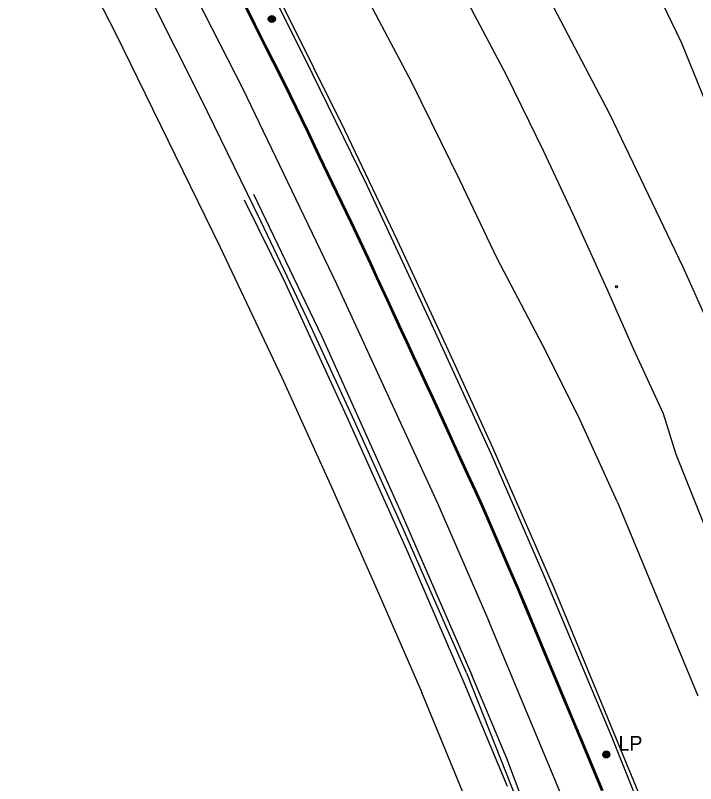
# Model space of a CAD drawing. Extents: x 368532 to 392481, y 10654822 to 10676899.
# Drawn here: x 370984.5 to 371215.5, y 10673594.7 to 10673855.7 of the extents above; entities that cross this region are included whole.
import ezdxf

# ---------------------------------------------------------------- set-up
doc = ezdxf.new("R2010")
doc.units = 0
for name, color, linetype in [('p_dtm sidewalk', 7, 'Continuous'), ('p_railroad rr control', 7, 'Continuous'), ('p_road - paved curb', 7, 'Continuous'), ('p_road conc barrier', 7, 'Continuous'), ('p_road dirt road', 7, 'Continuous'), ('p_road paint stripe', 7, 'Continuous'), ('p_structure unidentified', 7, 'Continuous'), ('p_utility general pole', 7, 'Continuous')]:
    doc.layers.add(name, color=color, linetype=linetype)

msp = doc.modelspace()

# ---------------------------------------------------------------- linework, layer by layer
at = {"layer": 'p_dtm sidewalk'}
for p, q in [((371085.43, 10673835.88), (371066.83, 10673873.16)), ((371103.96, 10673797.86), (371085.43, 10673835.88)), ((371126.54, 10673749.38), (371103.96, 10673797.86)), ((371146.19, 10673706.45), (371126.54, 10673749.38)), ((371164.1, 10673665.27), (371146.19, 10673706.45)), ((371187.05, 10673610.6), (371164.1, 10673665.27)), ((371215.53, 10673539.99), (371187.05, 10673610.6))]:
    msp.add_line(p, q, dxfattribs=at)
at = {"layer": 'p_railroad rr control'}
for points in [[(371246.16, 10673746.35), (371230.61, 10673793.15), (371219.17, 10673825.83), (371210.77, 10673846.5), (371202.64, 10673863.48), (371194.91, 10673877.5), (371181.49, 10673900.43), (371168.92, 10673920.49), (371158.22, 10673936.88), (371147.97, 10673951.26), (371140.55, 10673960.54)], [(371121.64, 10673939.77), (371155.42, 10673881.24), (371186.36, 10673821.96), (371211.08, 10673770.49), (371229.15, 10673730.13)]]:
    msp.add_lwpolyline(points, dxfattribs=at)
at = {"layer": 'p_road - paved curb'}
for p, q in [((371065.78, 10673852.48), (371062.66, 10673858.67)), ((371066.1, 10673852.63), (371062.98, 10673858.82)), ((371069.85, 10673844.32), (371065.78, 10673852.48)), ((371070.17, 10673844.47), (371066.1, 10673852.63)), ((371074.07, 10673835.87), (371069.85, 10673844.32)), ((371074.39, 10673836.02), (371070.17, 10673844.47)), ((371077.83, 10673828.31), (371074.07, 10673835.87)), ((371078.15, 10673828.46), (371074.39, 10673836.02)), ((371081.82, 10673820.2), (371077.83, 10673828.31)), ((371082.13, 10673820.35), (371078.15, 10673828.46)), ((371083.85, 10673815.93), (371081.82, 10673820.2)), ((371084.16, 10673816.08), (371082.13, 10673820.35)), ((371087.74, 10673807.71), (371083.85, 10673815.93)), ((371088.05, 10673807.87), (371084.16, 10673816.08)), ((371093.94, 10673795.65), (371088.05, 10673807.87)), ((371093.63, 10673795.5), (371087.74, 10673807.71)), ((371065.36, 10673794.93), (371088.63, 10673746.55)), ((371098.58, 10673785.19), (371093.63, 10673795.5)), ((371098.89, 10673785.34), (371093.94, 10673795.65)), ((371076.28, 10673764.68), (371062.35, 10673792.86)), ((371105.12, 10673771.23), (371098.58, 10673785.19)), ((371105.43, 10673771.38), (371098.89, 10673785.34)), ((371107.34, 10673766.41), (371105.12, 10673771.23)), ((371107.65, 10673766.56), (371105.43, 10673771.38)), ((371110.83, 10673758.94), (371107.34, 10673766.41)), ((371111.14, 10673759.09), (371107.65, 10673766.56)), ((371097.04, 10673719.36), (371076.28, 10673764.68)), ((371113.52, 10673753.02), (371110.83, 10673758.94)), ((371113.83, 10673753.17), (371111.14, 10673759.09)), ((371115.48, 10673748.84), (371113.52, 10673753.02)), ((371115.79, 10673748.99), (371113.83, 10673753.17)), ((371117.49, 10673744.53), (371115.48, 10673748.84)), ((371117.8, 10673744.68), (371115.79, 10673748.99)), ((371088.63, 10673746.55), (371115.11, 10673687.64)), ((371119.79, 10673739.54), (371117.49, 10673744.53)), ((371120.1, 10673739.69), (371117.8, 10673744.68)), ((371121.77, 10673735.24), (371119.79, 10673739.54)), ((371122.08, 10673735.39), (371120.1, 10673739.69)), ((371124.38, 10673729.59), (371121.77, 10673735.24)), ((371124.69, 10673729.74), (371122.08, 10673735.39)), ((371126.27, 10673725.52), (371124.38, 10673729.59)), ((371126.58, 10673725.67), (371124.69, 10673729.74)), ((371128.76, 10673720.04), (371126.27, 10673725.52)), ((371129.07, 10673720.19), (371126.58, 10673725.67)), ((371117.86, 10673673.07), (371097.04, 10673719.36)), ((371131.03, 10673715.09), (371128.76, 10673720.04)), ((371131.34, 10673715.24), (371129.07, 10673720.19)), ((371133.46, 10673709.79), (371131.03, 10673715.09)), ((371133.77, 10673709.94), (371131.34, 10673715.24)), ((371135.52, 10673705.29), (371133.46, 10673709.79)), ((371135.83, 10673705.44), (371133.77, 10673709.94)), ((371138.09, 10673699.69), (371135.52, 10673705.29)), ((371138.4, 10673699.84), (371135.83, 10673705.44)), ((371140.6, 10673694.28), (371138.09, 10673699.69)), ((371140.91, 10673694.43), (371138.4, 10673699.84)), ((371142.98, 10673689.1), (371140.6, 10673694.28)), ((371143.3, 10673689.25), (371140.91, 10673694.43)), ((371144.92, 10673684.71), (371142.98, 10673689.1)), ((371145.24, 10673684.85), (371143.3, 10673689.25)), ((371115.11, 10673687.64), (371139.48, 10673631.53)), ((371147.29, 10673679.16), (371144.92, 10673684.71)), ((371147.61, 10673679.3), (371145.24, 10673684.85)), ((371150.07, 10673672.61), (371147.29, 10673679.16)), ((371150.39, 10673672.75), (371147.61, 10673679.3)), ((371136.89, 10673628.95), (371117.86, 10673673.07)), ((371152.47, 10673667.06), (371150.07, 10673672.61)), ((371152.79, 10673667.2), (371150.39, 10673672.75)), ((371155.02, 10673661.09), (371152.47, 10673667.06)), ((371155.34, 10673661.23), (371152.79, 10673667.2)), ((371157.73, 10673654.75), (371155.02, 10673661.09)), ((371158.05, 10673654.88), (371155.34, 10673661.23)), ((371159.82, 10673649.75), (371157.73, 10673654.75)), ((371160.14, 10673649.88), (371158.05, 10673654.88)), ((371162.34, 10673643.73), (371159.82, 10673649.75)), ((371162.66, 10673643.86), (371160.14, 10673649.88)), ((371164.51, 10673638.5), (371162.34, 10673643.73)), ((371164.83, 10673638.63), (371162.66, 10673643.86)), ((371166.88, 10673632.85), (371164.51, 10673638.5)), ((371167.2, 10673632.98), (371164.83, 10673638.63)), ((371169.55, 10673627.32), (371167.2, 10673632.98)), ((371151.37, 10673603.16), (371139.48, 10673631.53)), ((371169.23, 10673627.19), (371166.88, 10673632.85)), ((371151.65, 10673593.69), (371136.89, 10673628.95)), ((371171.15, 10673622.57), (371169.23, 10673627.19)), ((371171.47, 10673622.7), (371169.55, 10673627.32)), ((371174.33, 10673615.02), (371171.15, 10673622.57)), ((371174.65, 10673615.15), (371171.47, 10673622.7)), ((371176.6, 10673609.61), (371174.33, 10673615.02)), ((371176.92, 10673609.74), (371174.65, 10673615.15)), ((371178.82, 10673604.21), (371176.6, 10673609.61)), ((371179.14, 10673604.34), (371176.92, 10673609.74)), ((371181.24, 10673598.45), (371178.82, 10673604.21)), ((371181.56, 10673598.58), (371179.14, 10673604.34)), ((371177.2, 10673535.77), (371151.37, 10673603.16)), ((371183.81, 10673592.22), (371181.24, 10673598.45)), ((371184.13, 10673592.35), (371181.56, 10673598.58))]:
    msp.add_line(p, q, dxfattribs=at)
msp.add_lwpolyline([(371183.67, 10673592.16), (371181.1, 10673598.39), (371178.68, 10673604.15), (371176.46, 10673609.55), (371174.19, 10673614.96), (371171.01, 10673622.51), (371169.09, 10673627.13), (371166.74, 10673632.79), (371164.37, 10673638.44), (371162.2, 10673643.67), (371159.68, 10673649.69), (371157.59, 10673654.69), (371154.88, 10673661.03), (371152.33, 10673667), (371149.93, 10673672.55), (371147.15, 10673679.1), (371144.78, 10673684.65), (371142.84, 10673689.04), (371140.46, 10673694.22), (371137.95, 10673699.63), (371135.38, 10673705.23), (371133.32, 10673709.73), (371130.89, 10673715.03), (371128.62, 10673719.98), (371126.13, 10673725.46), (371124.24, 10673729.53), (371121.63, 10673735.18), (371119.65, 10673739.48), (371117.35, 10673744.47), (371115.34, 10673748.78), (371113.38, 10673752.96), (371110.69, 10673758.88), (371107.2, 10673766.35), (371104.98, 10673771.17), (371098.44, 10673785.13), (371093.49, 10673795.43), (371087.6, 10673807.65), (371083.71, 10673815.87), (371081.68, 10673820.13), (371077.7, 10673828.24), (371073.94, 10673835.8), (371069.72, 10673844.25), (371065.65, 10673852.41), (371062.53, 10673858.6)], dxfattribs=at)
at = {"layer": 'p_road conc barrier'}
for p, q in [((371047.53, 10673827.58), (371026.43, 10673869.44)), ((371075.16, 10673859.35), (371096.26, 10673816.75)), ((371067.88, 10673785.81), (371047.53, 10673827.58)), ((371096.26, 10673816.75), (371114.15, 10673779.3)), ((371083.52, 10673752.95), (371067.88, 10673785.81)), ((371114.15, 10673779.3), (371131.39, 10673742.17)), ((371099.05, 10673719.27), (371083.52, 10673752.95)), ((371131.39, 10673742.17), (371146.64, 10673708.65)), ((371115.77, 10673682.22), (371099.05, 10673719.27)), ((371146.64, 10673708.65), (371167.14, 10673661.74)), ((371137.69, 10673632.32), (371115.77, 10673682.22)), ((371167.14, 10673661.74), (371208.59, 10673561.49)), ((371137.69, 10673632.32), (371195.39, 10673486.38))]:
    msp.add_line(p, q, dxfattribs=at)
at = {"layer": 'p_road dirt road'}
for p, q in [((371136.88, 10673862.63), (371151.33, 10673835.23)), ((371119.21, 10673832.86), (371103.6, 10673862.36)), ((371151.33, 10673835.23), (371163.83, 10673809.51)), ((371135.58, 10673799.43), (371119.21, 10673832.86)), ((371163.83, 10673809.51), (371173.69, 10673788.54)), ((371148.09, 10673773.12), (371135.58, 10673799.43)), ((371173.69, 10673788.54), (371185.42, 10673762.77)), ((371163.58, 10673743.78), (371148.09, 10673773.12)), ((371185.42, 10673762.77), (371194.33, 10673742.55)), ((371175.71, 10673719.43), (371163.58, 10673743.78)), ((371194.33, 10673742.55), (371204.56, 10673720.38)), ((371188.9, 10673690.51), (371175.71, 10673719.43)), ((371204.56, 10673720.38), (371208.79, 10673706.6)), ((371208.79, 10673706.6), (371238.92, 10673630.97)), ((371188.9, 10673690.51), (371216.28, 10673624.47))]:
    msp.add_line(p, q, dxfattribs=at)
at = {"layer": 'p_road paint stripe'}
for p, q in [((370984.51, 10673915.41), (371018.56, 10673849.63)), ((371043.86, 10673865.92), (371061.78, 10673830.7)), ((371018.56, 10673849.63), (371054.09, 10673776.9)), ((371061.78, 10673830.7), (371093.57, 10673764.46)), ((371054.09, 10673776.9), (371074.97, 10673732.67)), ((371093.57, 10673764.46), (371127.9, 10673689.94)), ((371074.97, 10673732.67), (371091.6, 10673696)), ((371091.6, 10673696), (371107.89, 10673659.41)), ((371127.9, 10673689.94), (371145.3, 10673649.84)), ((371107.89, 10673659.41), (371122.52, 10673625.61)), ((371188.25, 10673546.89), (371145.3, 10673649.84)), ((371151.56, 10673555.44), (371122.52, 10673625.61))]:
    msp.add_line(p, q, dxfattribs=at)
at = {"layer": 'p_structure unidentified'}
msp.add_circle((371188.66, 10673763.52), 0.375, dxfattribs=at)
at = {"layer": 'p_utility general pole'}
for centre, radius in [((371071.61, 10673854.45), 1.19), ((371071.61, 10673854.45), 0.901), ((371071.61, 10673854.45), 0.608), ((371071.61, 10673854.45), 0.337), ((371071.61, 10673854.45), 0.12), ((371185.19, 10673604.58), 1.19), ((371185.19, 10673604.58), 0.901), ((371185.19, 10673604.58), 0.608), ((371185.19, 10673604.58), 0.337), ((371185.19, 10673604.58), 0.12)]:
    msp.add_circle(centre, radius, dxfattribs=at)

# ---------------------------------------------------------------- texts
msp.add_text('LP', height=5, dxfattribs=at).set_placement((371189.31, 10673605.87))

doc.saveas('drawing.dxf')
